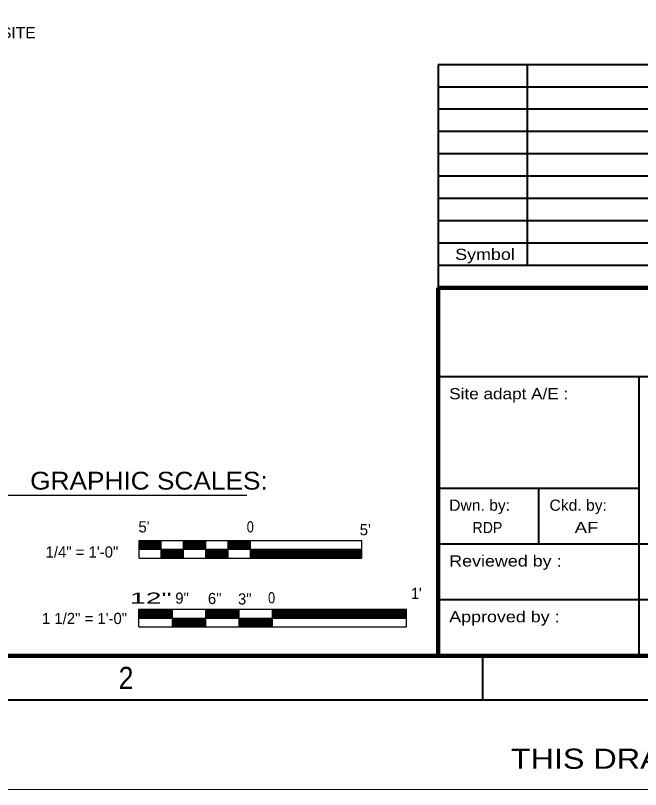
# Model space of a CAD drawing. Extents: x -22.3 to 19.7, y -11.8 to 18.2.
# Drawn here: x 5.45 to 12.46, y -11.84 to -3.16 of the extents above; entities that cross this region are included whole.
import ezdxf
from ezdxf.enums import TextEntityAlignment as Align

# ---------------------------------------------------------------- set-up
doc = ezdxf.new("R2010")
doc.units = 0
doc.header["$LTSCALE"] = 0.05
doc.layers.add('1', color=7, linetype='Continuous', lineweight=13)
doc.layers.add('2', color=7, linetype='Continuous', lineweight=13)

msp = doc.modelspace()

# ---------------------------------------------------------------- linework, layer by layer
at = {"layer": '1', "lineweight": 40}
for p, q in [((10.19058, -3.71469), (10.19058, -6.21469)), ((18.19058, -3.71469), (10.19058, -3.71469)), ((11.19058, -3.71469), (11.19058, -5.96469)), ((18.19058, -3.96469), (10.19058, -3.96469)), ((18.19058, -4.21469), (10.19058, -4.21469)), ((18.19058, -4.46469), (10.19058, -4.46469)), ((18.19058, -4.71469), (10.19058, -4.71469)), ((18.19058, -4.96469), (10.19058, -4.96469)), ((18.19058, -5.21469), (10.19058, -5.21469)), ((18.19058, -5.46469), (10.19058, -5.46469)), ((18.19058, -5.71469), (10.19058, -5.71469)), ((18.19058, -5.96469), (10.19058, -5.96469)), ((18.19058, -7.21469), (10.19058, -7.21469)), ((12.44058, -7.21469), (12.44058, -10.33969)), ((12.44058, -8.46469), (10.19058, -8.46469)), ((11.31558, -8.46469), (11.31558, -9.08969)), ((18.19058, -9.08969), (10.19058, -9.08969)), ((14.62858, -9.71469), (10.19058, -9.71469)), ((10.69058, -10.33969), (10.69058, -10.83969))]:
    msp.add_line(p, q, dxfattribs=at)
at = {"layer": '1', "lineweight": 90}
for p, q in [((10.19058, -6.21469), (10.19058, -10.33969)), ((18.19058, -6.21469), (10.19058, -6.21469))]:
    msp.add_line(p, q, dxfattribs=at)
at = {"layer": '1', "lineweight": 25}
for p, q in [((5.20158, -8.54069), (8.04558, -8.54069)), ((6.83658, -9.04669), (9.33658, -9.04669)), ((6.83658, -9.24669), (6.83658, -9.04669)), ((6.83658, -9.05069), (7.08658, -9.05069)), ((6.83658, -9.05569), (7.08658, -9.05569)), ((6.83658, -9.06069), (7.08658, -9.06069)), ((6.83658, -9.06569), (7.08658, -9.06569)), ((6.83658, -9.07069), (7.08658, -9.07069)), ((6.83658, -9.07569), (7.08658, -9.07569)), ((6.83658, -9.08069), (7.08658, -9.08069)), ((6.83658, -9.08569), (7.08658, -9.08569)), ((6.83658, -9.09069), (7.08658, -9.09069)), ((6.83658, -9.09569), (7.08658, -9.09569)), ((6.83658, -9.10069), (7.08658, -9.10069)), ((6.83658, -9.10569), (7.08658, -9.10569)), ((6.83658, -9.11069), (7.08658, -9.11069)), ((7.08658, -9.24669), (7.08658, -9.04669)), ((7.33658, -9.24669), (7.33658, -9.04669)), ((7.33658, -9.05069), (7.58658, -9.05069)), ((7.33658, -9.05569), (7.58658, -9.05569)), ((7.33658, -9.06069), (7.58658, -9.06069)), ((7.33658, -9.06569), (7.58658, -9.06569)), ((7.33658, -9.07069), (7.58658, -9.07069)), ((7.33658, -9.07569), (7.58658, -9.07569)), ((7.33658, -9.08069), (7.58658, -9.08069)), ((7.33658, -9.08569), (7.58658, -9.08569)), ((7.33658, -9.09069), (7.58658, -9.09069)), ((7.33658, -9.09569), (7.58658, -9.09569)), ((7.33658, -9.10069), (7.58658, -9.10069)), ((7.33658, -9.10569), (7.58658, -9.10569)), ((7.33658, -9.11069), (7.58658, -9.11069)), ((7.58658, -9.24669), (7.58658, -9.04669)), ((7.83658, -9.24669), (7.83658, -9.04669)), ((7.83658, -9.05069), (8.08658, -9.05069)), ((7.83658, -9.05569), (8.08658, -9.05569)), ((7.83658, -9.06069), (8.08658, -9.06069)), ((7.83658, -9.06569), (8.08658, -9.06569)), ((7.83658, -9.07069), (8.08658, -9.07069)), ((7.83658, -9.07569), (8.08658, -9.07569)), ((7.83658, -9.08069), (8.08658, -9.08069)), ((7.83658, -9.08569), (8.08658, -9.08569)), ((7.83658, -9.09069), (8.08658, -9.09069)), ((7.83658, -9.09569), (8.08658, -9.09569)), ((7.83658, -9.10069), (8.08658, -9.10069)), ((7.83658, -9.10569), (8.08658, -9.10569)), ((7.83658, -9.11069), (8.08658, -9.11069)), ((8.08658, -9.24669), (8.08658, -9.04669)), ((9.33658, -9.24669), (9.33658, -9.04669)), ((6.83658, -9.11569), (7.08658, -9.11569)), ((6.83658, -9.12069), (7.08658, -9.12069)), ((6.83658, -9.12569), (7.08658, -9.12569)), ((6.83658, -9.13069), (7.08658, -9.13069)), ((6.83658, -9.13569), (7.08658, -9.13569)), ((6.83658, -9.14069), (7.08658, -9.14069)), ((6.83658, -9.14669), (9.33658, -9.14669)), ((7.08658, -9.15269), (7.33658, -9.15269)), ((7.08658, -9.15869), (7.33658, -9.15869)), ((7.08658, -9.16469), (7.33658, -9.16469)), ((7.08658, -9.17269), (7.33658, -9.17269)), ((7.08658, -9.18069), (7.33658, -9.18069)), ((7.08658, -9.18769), (7.33658, -9.18769)), ((7.08658, -9.19569), (7.33658, -9.19569)), ((7.33658, -9.11569), (7.58658, -9.11569)), ((7.33658, -9.12069), (7.58658, -9.12069)), ((7.33658, -9.12569), (7.58658, -9.12569)), ((7.33658, -9.13069), (7.58658, -9.13069)), ((7.33658, -9.13569), (7.58658, -9.13569)), ((7.33658, -9.14069), (7.58658, -9.14069)), ((7.58658, -9.15269), (7.83658, -9.15269)), ((7.58658, -9.15869), (7.83658, -9.15869)), ((7.58658, -9.16469), (7.83658, -9.16469)), ((7.58658, -9.17269), (7.83658, -9.17269)), ((7.58658, -9.18069), (7.83658, -9.18069)), ((7.58658, -9.18769), (7.83658, -9.18769)), ((7.58658, -9.19569), (7.83658, -9.19569)), ((7.83658, -9.11569), (8.08658, -9.11569)), ((7.83658, -9.12069), (8.08658, -9.12069)), ((7.83658, -9.12569), (8.08658, -9.12569)), ((7.83658, -9.13069), (8.08658, -9.13069)), ((7.83658, -9.13569), (8.08658, -9.13569)), ((7.83658, -9.14069), (8.08658, -9.14069)), ((8.08658, -9.15269), (9.33658, -9.15269)), ((8.08658, -9.15569), (9.33658, -9.15569)), ((8.08658, -9.16169), (9.33658, -9.16169)), ((8.08658, -9.16669), (9.33658, -9.16669)), ((8.08658, -9.17369), (9.33658, -9.17369)), ((8.08658, -9.17869), (9.33658, -9.17869)), ((8.08658, -9.18669), (9.33658, -9.18669)), ((8.08658, -9.19269), (9.33658, -9.19269)), ((6.83658, -9.24669), (9.33658, -9.24669)), ((7.08658, -9.20469), (7.33658, -9.20469)), ((7.08658, -9.21169), (7.33658, -9.21169)), ((7.08658, -9.22069), (7.33658, -9.22069)), ((7.08658, -9.22869), (7.33658, -9.22869)), ((7.08658, -9.23569), (7.33658, -9.23569)), ((7.58658, -9.20469), (7.83658, -9.20469)), ((7.58658, -9.21169), (7.83658, -9.21169)), ((7.58658, -9.22069), (7.83658, -9.22069)), ((7.58658, -9.22869), (7.83658, -9.22869)), ((7.58658, -9.23569), (7.83658, -9.23569)), ((8.08658, -9.20069), (9.33658, -9.20069)), ((8.08658, -9.20569), (9.33658, -9.20569)), ((8.08658, -9.21269), (9.33658, -9.21269)), ((8.08658, -9.21869), (9.33658, -9.21869)), ((8.08658, -9.22369), (9.33658, -9.22369)), ((8.08658, -9.22969), (9.33658, -9.22969)), ((8.08658, -9.23569), (9.33658, -9.23569)), ((6.83558, -9.81769), (9.83558, -9.81769)), ((6.83558, -10.01769), (6.83558, -9.81769)), ((6.83558, -9.82269), (7.21058, -9.82269)), ((6.83558, -9.82769), (7.21058, -9.82769)), ((6.83558, -9.83269), (7.21058, -9.83269)), ((6.83558, -9.83769), (7.21058, -9.83769)), ((6.83558, -9.84269), (7.21058, -9.84269)), ((6.83558, -9.84769), (7.21058, -9.84769)), ((6.83558, -9.85269), (7.21058, -9.85269)), ((6.83558, -9.85769), (7.21058, -9.85769)), ((6.83558, -9.86269), (7.21058, -9.86269)), ((6.83558, -9.86769), (7.21058, -9.86769)), ((6.83558, -9.87269), (7.21058, -9.87269)), ((6.83558, -9.87769), (7.21058, -9.87769)), ((6.83558, -9.88269), (7.21058, -9.88269)), ((6.83558, -9.88769), (7.21058, -9.88769)), ((7.21058, -10.01769), (7.21058, -9.81769)), ((7.58558, -10.01769), (7.58558, -9.81769)), ((7.58558, -9.82269), (7.96058, -9.82269)), ((7.58558, -9.82769), (7.96058, -9.82769)), ((7.58558, -9.83269), (7.96058, -9.83269)), ((7.58558, -9.83769), (7.96058, -9.83769)), ((7.58558, -9.84269), (7.96058, -9.84269)), ((7.58558, -9.84769), (7.96058, -9.84769)), ((7.58558, -9.85269), (7.96058, -9.85269)), ((7.58558, -9.85769), (7.96058, -9.85769)), ((7.58558, -9.86269), (7.96058, -9.86269)), ((7.58558, -9.86769), (7.96058, -9.86769)), ((7.58558, -9.87269), (7.96058, -9.87269)), ((7.58558, -9.87769), (7.96058, -9.87769)), ((7.58558, -9.88269), (7.96058, -9.88269)), ((7.58558, -9.88769), (7.96058, -9.88769)), ((7.96058, -10.01769), (7.96058, -9.81769)), ((8.33558, -10.01769), (8.33558, -9.81769)), ((8.33558, -9.82269), (9.83558, -9.82269)), ((8.33558, -9.82769), (9.83558, -9.82769)), ((8.33558, -9.83269), (9.83558, -9.83269)), ((8.33558, -9.83769), (9.83558, -9.83769)), ((8.33558, -9.84269), (9.83558, -9.84269)), ((8.33558, -9.84769), (9.83558, -9.84769)), ((8.33558, -9.85269), (9.83558, -9.85269)), ((8.33558, -9.85769), (9.83558, -9.85769)), ((8.33558, -9.86269), (9.83558, -9.86269)), ((8.33558, -9.86769), (9.83558, -9.86769)), ((8.33558, -9.87269), (9.83558, -9.87269)), ((8.33558, -9.87769), (9.83558, -9.87769)), ((8.33558, -9.88269), (9.83558, -9.88269)), ((8.33558, -9.88769), (9.83558, -9.88769)), ((9.83558, -10.01769), (9.83558, -9.81769)), ((6.83558, -9.89269), (7.21058, -9.89269)), ((6.83558, -9.89769), (7.21058, -9.89769)), ((6.83558, -9.90269), (7.21058, -9.90269)), ((6.83558, -9.90769), (7.21058, -9.90769)), ((6.83558, -9.91269), (7.21058, -9.91269)), ((6.83558, -9.91769), (9.83558, -9.91769)), ((7.21058, -9.92269), (7.58558, -9.92269)), ((7.21058, -9.92769), (7.58558, -9.92769)), ((7.21058, -9.93269), (7.58558, -9.93269)), ((7.21058, -9.93769), (7.58558, -9.93769)), ((7.21058, -9.94269), (7.58558, -9.94269)), ((7.21058, -9.94769), (7.58558, -9.94769)), ((7.21058, -9.95269), (7.58558, -9.95269)), ((7.21058, -9.95769), (7.58558, -9.95769)), ((7.21058, -9.96269), (7.58558, -9.96269)), ((7.21058, -9.96769), (7.58558, -9.96769)), ((7.21058, -9.97269), (7.58558, -9.97269)), ((7.21058, -9.97769), (7.58558, -9.97769)), ((7.58558, -9.89269), (7.96058, -9.89269)), ((7.58558, -9.89769), (7.96058, -9.89769)), ((7.58558, -9.90269), (7.96058, -9.90269)), ((7.58558, -9.90769), (7.96058, -9.90769)), ((7.58558, -9.91269), (7.96058, -9.91269)), ((7.96058, -9.91769), (8.33558, -9.91769)), ((7.96058, -9.92269), (8.33558, -9.92269)), ((7.96058, -9.92769), (8.33558, -9.92769)), ((7.96058, -9.93269), (8.33558, -9.93269)), ((7.96058, -9.93769), (8.33558, -9.93769)), ((7.96058, -9.94269), (8.33558, -9.94269)), ((7.96058, -9.94769), (8.33558, -9.94769)), ((7.96058, -9.95269), (8.33558, -9.95269)), ((7.96058, -9.95769), (8.33558, -9.95769)), ((7.96058, -9.96269), (8.33558, -9.96269)), ((7.96058, -9.96769), (8.33558, -9.96769)), ((7.96058, -9.97269), (8.33558, -9.97269)), ((7.96058, -9.97769), (8.33558, -9.97769)), ((8.33558, -9.89269), (9.83558, -9.89269)), ((8.33558, -9.89769), (9.83558, -9.89769)), ((8.33558, -9.90269), (9.83558, -9.90269)), ((8.33558, -9.90769), (9.83558, -9.90769)), ((8.33558, -9.91269), (9.83558, -9.91269)), ((6.83558, -10.01769), (9.83558, -10.01769)), ((7.21058, -9.98269), (7.58558, -9.98269)), ((7.21058, -9.98769), (7.58558, -9.98769)), ((7.21058, -9.99269), (7.58558, -9.99269)), ((7.21058, -9.99769), (7.58558, -9.99769)), ((7.21058, -10.00269), (7.58558, -10.00269)), ((7.21058, -10.00769), (7.58558, -10.00769)), ((7.21058, -10.01269), (7.58558, -10.01269)), ((7.96058, -9.98269), (8.33558, -9.98269)), ((7.96058, -9.98769), (8.33558, -9.98769)), ((7.96058, -9.99269), (8.33558, -9.99269)), ((7.96058, -9.99769), (8.33558, -9.99769)), ((7.96058, -10.00269), (8.33558, -10.00269)), ((7.96058, -10.00769), (8.33558, -10.00769)), ((7.96058, -10.01269), (8.33558, -10.01269))]:
    msp.add_line(p, q, dxfattribs=at)
at = {"layer": '1'}
msp.add_line((19.69058, -11.83969), (-22.30942, -11.83969), dxfattribs=at)
at = {"layer": '1', "lineweight": 40}
msp.add_lwpolyline([(-21.30942, -10.83969), (-21.30942, 17.16031), (18.69058, 17.16031), (18.69058, -10.83969)], close=True, dxfattribs=at)
at = {"layer": '1', "lineweight": 90}
msp.add_lwpolyline([(-19.80942, 16.66031), (18.19058, 16.66031), (18.19058, -10.33969), (-19.80942, -10.33969)], close=True, dxfattribs=at)

# ---------------------------------------------------------------- texts
at = {"layer": '1'}
for s, width, p in [('DRAINAGE COMPOSITE', 1.05, (3.65958, -3.41769)), ('Site adapt A/E :', 1.15, (10.31558, -7.46469)), ('Dwn. by:', 1.05, (10.31558, -8.71469)), ('Ckd. by:', 1.05, (11.44058, -8.71469)), ('Reviewed by :', 1.2, (10.31558, -9.33969)), ('Approved by :', 1.2, (10.31558, -9.96469))]:
    msp.add_text(s, height=0.125, dxfattribs=dict(at, width=width)).set_placement(p)
for s, height, width, p in [('Symbol', 0.125, 1.2, (10.71708, -5.90269)), ('0', 0.125, 0.85, (8.08458, -8.95769)), ('2', 0.25, 0.9, (6.69108, -10.71469)), ('THIS DRAWING SUPERSEDES STD 33-15-73', 0.226, 1.2, (14.82508, -11.60769))]:
    msp.add_text(s, height=height, dxfattribs=dict(at, width=width)).set_placement(p, align=Align.CENTER)
at = {"layer": '1', "width": 1.1}
msp.add_text('GRAPHIC SCALES:', height=0.2, dxfattribs=at).set_placement((8.28058, -8.47769), align=Align.RIGHT)
at = {"layer": '1'}
for p in [(6.89258, -8.95769), (9.37458, -8.98969)]:
    msp.add_text("5'", height=0.125, dxfattribs=at).set_placement(p, align=Align.CENTER)
for s, p in [('1/4" = 1\'-0"', (6.60358, -9.23969)), ('1 1/2" = 1\'-0"', (6.70258, -9.98469))]:
    msp.add_text(s, height=0.125, dxfattribs=at).set_placement(p, align=Align.RIGHT)
at = {"layer": '2'}
for s, width, p in [('RDP', 0.95, (10.74408, -8.96569)), ('AF ', 1.25, (11.88508, -8.96469)), ('12"', 1.9, (6.96858, -9.75669)), ('0', 0.85, (8.32358, -9.75269)), ("1'", 0.95, (9.94758, -9.70269))]:
    msp.add_text(s, height=0.125, dxfattribs=dict(at, width=width)).set_placement(p, align=Align.CENTER)
for s, p in [('9"', (7.31958, -9.75669)), ('6"', (7.68558, -9.76069)), ('3"', (8.02258, -9.76569))]:
    msp.add_text(s, height=0.125, dxfattribs=at).set_placement(p, align=Align.CENTER)

doc.saveas('drawing.dxf')
